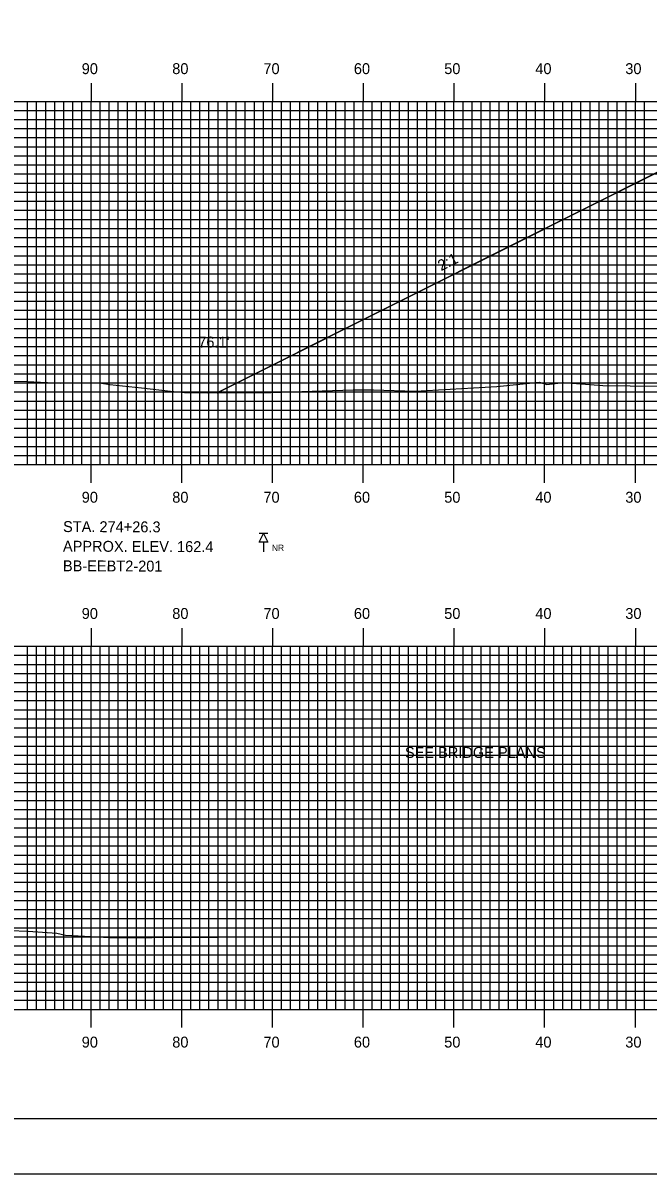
# Model space of a CAD drawing. Extents: x 1809406 to 1809749, y 442591 to 442811.
# Drawn here: x 1809474.3 to 1809543.2, y 442590.5 to 442717.3 of the extents above; entities that cross this region are included whole.
import ezdxf

# ---------------------------------------------------------------- set-up
doc = ezdxf.new("R2010")
doc.units = 0
for name, color, linetype in [('ANNOTATION', 7, 'Continuous'), ('BORDER', 7, 'Continuous'), ('BORING - NO REFUSAL', 7, 'Continuous'), ('D_Roadway_Centerline', 7, 'Continuous'), ('D_Roadway_SlopeLines', 7, 'Continuous'), ('D_Text_Standard', 7, 'Continuous'), ('H_V ANNOTATION', 7, 'Continuous'), ('MAJOR', 7, 'Continuous'), ('MINOR', 7, 'Continuous'), ('PLOT BOUNDARY', 7, 'Continuous'), ('S_Roadway_Centerline', 7, 'Continuous')]:
    doc.layers.add(name, color=color, linetype=linetype)

msp = doc.modelspace()

# ---------------------------------------------------------------- linework, layer by layer
at = {"layer": 'BORDER'}
msp.add_lwpolyline([(1809422.24, 442596.67), (1809742.24, 442596.67), (1809742.24, 442806.67), (1809422.24, 442806.67)], close=True, dxfattribs=at)
at = {"layer": 'BORING - NO REFUSAL'}
for p, q in [((1809501.32, 442661.07), (1809500.36, 442661.07)), ((1809500.84, 442660.11), (1809500.84, 442659.05))]:
    msp.add_line(p, q, dxfattribs=at)
msp.add_lwpolyline([(1809500.84, 442661.07), (1809501.32, 442660.11), (1809500.36, 442660.11)], close=True, dxfattribs=at)
at = {"layer": 'D_Roadway_Centerline'}
msp.add_lwpolyline([(1809495.74, 442676.58), (1809543.88, 442700.65), (1809548.84, 442703.13), (1809551.84, 442703.22), (1809559.84, 442703.47), (1809571.84, 442703.12), (1809583.84, 442702.77), (1809591.84, 442702.45), (1809594.84, 442702.33), (1809599.89, 442699.8), (1809643.63, 442677.93)], dxfattribs=at)
at = {"layer": 'D_Roadway_SlopeLines'}
msp.add_lwpolyline([(1809548.84, 442703.13), (1809495.74, 442676.58)], dxfattribs=at)
at = {"layer": 'MAJOR'}
for p, q in [((1809481.84, 442710.67), (1809481.84, 442708.67)), ((1809491.84, 442710.67), (1809491.84, 442708.67)), ((1809501.84, 442710.67), (1809501.84, 442708.67)), ((1809511.84, 442710.67), (1809511.84, 442708.67)), ((1809521.84, 442710.67), (1809521.84, 442708.67)), ((1809531.84, 442710.67), (1809531.84, 442708.67)), ((1809541.84, 442710.67), (1809541.84, 442708.67)), ((1809431.84, 442708.67), (1809711.84, 442708.67)), ((1809431.84, 442708.67), (1809711.84, 442708.67)), ((1809481.84, 442668.67), (1809481.84, 442708.67)), ((1809491.84, 442668.67), (1809491.84, 442708.67)), ((1809501.84, 442668.67), (1809501.84, 442708.67)), ((1809511.84, 442668.67), (1809511.84, 442708.67)), ((1809521.84, 442668.67), (1809521.84, 442708.67)), ((1809531.84, 442668.67), (1809531.84, 442708.67)), ((1809541.84, 442668.67), (1809541.84, 442708.67)), ((1809431.84, 442703.67), (1809711.84, 442703.67)), ((1809431.84, 442698.67), (1809711.84, 442698.67)), ((1809431.84, 442693.67), (1809711.84, 442693.67)), ((1809431.84, 442688.67), (1809711.84, 442688.67)), ((1809431.84, 442683.67), (1809711.84, 442683.67)), ((1809431.84, 442678.67), (1809711.84, 442678.67)), ((1809431.84, 442673.67), (1809711.84, 442673.67)), ((1809431.84, 442668.67), (1809711.84, 442668.67)), ((1809431.84, 442668.67), (1809711.84, 442668.67)), ((1809481.84, 442666.66), (1809481.84, 442668.67)), ((1809491.84, 442666.66), (1809491.84, 442668.67)), ((1809501.84, 442666.66), (1809501.84, 442668.67)), ((1809511.84, 442666.66), (1809511.84, 442668.67)), ((1809521.84, 442666.66), (1809521.84, 442668.67)), ((1809531.84, 442666.66), (1809531.84, 442668.67)), ((1809541.84, 442666.66), (1809541.84, 442668.67)), ((1809481.84, 442650.67), (1809481.84, 442648.67)), ((1809491.84, 442650.67), (1809491.84, 442648.67)), ((1809501.84, 442650.67), (1809501.84, 442648.67)), ((1809511.84, 442650.67), (1809511.84, 442648.67)), ((1809521.84, 442650.67), (1809521.84, 442648.67)), ((1809531.84, 442650.67), (1809531.84, 442648.67)), ((1809541.84, 442650.67), (1809541.84, 442648.67)), ((1809431.84, 442648.67), (1809711.84, 442648.67)), ((1809431.84, 442648.67), (1809711.84, 442648.67)), ((1809481.84, 442608.67), (1809481.84, 442648.67)), ((1809491.84, 442608.67), (1809491.84, 442648.67)), ((1809501.84, 442608.67), (1809501.84, 442648.67)), ((1809511.84, 442608.67), (1809511.84, 442648.67)), ((1809521.84, 442608.67), (1809521.84, 442648.67)), ((1809531.84, 442608.67), (1809531.84, 442648.67)), ((1809541.84, 442608.67), (1809541.84, 442648.67)), ((1809431.84, 442643.67), (1809711.84, 442643.67)), ((1809431.84, 442638.67), (1809711.84, 442638.67)), ((1809431.84, 442633.67), (1809711.84, 442633.67)), ((1809431.84, 442628.67), (1809711.84, 442628.67)), ((1809431.84, 442623.67), (1809711.84, 442623.67)), ((1809431.84, 442618.67), (1809711.84, 442618.67)), ((1809431.84, 442613.67), (1809711.84, 442613.67)), ((1809431.84, 442608.67), (1809711.84, 442608.67)), ((1809431.84, 442608.67), (1809711.84, 442608.67)), ((1809481.84, 442606.66), (1809481.84, 442608.67)), ((1809491.84, 442606.66), (1809491.84, 442608.67)), ((1809501.84, 442606.66), (1809501.84, 442608.67)), ((1809511.84, 442606.66), (1809511.84, 442608.67)), ((1809521.84, 442606.66), (1809521.84, 442608.67)), ((1809531.84, 442606.66), (1809531.84, 442608.67)), ((1809541.84, 442606.66), (1809541.84, 442608.67))]:
    msp.add_line(p, q, dxfattribs=at)
at = {"layer": 'MINOR'}
for p, q in [((1809474.84, 442668.67), (1809474.84, 442708.67)), ((1809475.84, 442668.67), (1809475.84, 442708.67)), ((1809476.84, 442668.67), (1809476.84, 442708.67)), ((1809477.84, 442668.67), (1809477.84, 442708.67)), ((1809478.84, 442668.67), (1809478.84, 442708.67)), ((1809479.84, 442668.67), (1809479.84, 442708.67)), ((1809480.84, 442668.67), (1809480.84, 442708.67)), ((1809482.84, 442668.67), (1809482.84, 442708.67)), ((1809483.84, 442668.67), (1809483.84, 442708.67)), ((1809484.84, 442668.67), (1809484.84, 442708.67)), ((1809485.84, 442668.67), (1809485.84, 442708.67)), ((1809486.84, 442668.67), (1809486.84, 442708.67)), ((1809487.84, 442668.67), (1809487.84, 442708.67)), ((1809488.84, 442668.67), (1809488.84, 442708.67)), ((1809489.84, 442668.67), (1809489.84, 442708.67)), ((1809490.84, 442668.67), (1809490.84, 442708.67)), ((1809492.84, 442668.67), (1809492.84, 442708.67)), ((1809493.84, 442668.67), (1809493.84, 442708.67)), ((1809494.84, 442668.67), (1809494.84, 442708.67)), ((1809495.84, 442668.67), (1809495.84, 442708.67)), ((1809496.84, 442668.67), (1809496.84, 442708.67)), ((1809497.84, 442668.67), (1809497.84, 442708.67)), ((1809498.84, 442668.67), (1809498.84, 442708.67)), ((1809499.84, 442668.67), (1809499.84, 442708.67)), ((1809500.84, 442668.67), (1809500.84, 442708.67)), ((1809502.84, 442668.67), (1809502.84, 442708.67)), ((1809503.84, 442668.67), (1809503.84, 442708.67)), ((1809504.84, 442668.67), (1809504.84, 442708.67)), ((1809505.84, 442668.67), (1809505.84, 442708.67)), ((1809506.84, 442668.67), (1809506.84, 442708.67)), ((1809507.84, 442668.67), (1809507.84, 442708.67)), ((1809508.84, 442668.67), (1809508.84, 442708.67)), ((1809509.84, 442668.67), (1809509.84, 442708.67)), ((1809510.84, 442668.67), (1809510.84, 442708.67)), ((1809512.84, 442668.67), (1809512.84, 442708.67)), ((1809513.84, 442668.67), (1809513.84, 442708.67)), ((1809514.84, 442668.67), (1809514.84, 442708.67)), ((1809515.84, 442668.67), (1809515.84, 442708.67)), ((1809516.84, 442668.67), (1809516.84, 442708.67)), ((1809517.84, 442668.67), (1809517.84, 442708.67)), ((1809518.84, 442668.67), (1809518.84, 442708.67)), ((1809519.84, 442668.67), (1809519.84, 442708.67)), ((1809520.84, 442668.67), (1809520.84, 442708.67)), ((1809522.84, 442668.67), (1809522.84, 442708.67)), ((1809523.84, 442668.67), (1809523.84, 442708.67)), ((1809524.84, 442668.67), (1809524.84, 442708.67)), ((1809525.84, 442668.67), (1809525.84, 442708.67)), ((1809526.84, 442668.67), (1809526.84, 442708.67)), ((1809527.84, 442668.67), (1809527.84, 442708.67)), ((1809528.84, 442668.67), (1809528.84, 442708.67)), ((1809529.84, 442668.67), (1809529.84, 442708.67)), ((1809530.84, 442668.67), (1809530.84, 442708.67)), ((1809532.84, 442668.67), (1809532.84, 442708.67)), ((1809533.84, 442668.67), (1809533.84, 442708.67)), ((1809534.84, 442668.67), (1809534.84, 442708.67)), ((1809535.84, 442668.67), (1809535.84, 442708.67)), ((1809536.84, 442668.67), (1809536.84, 442708.67)), ((1809537.84, 442668.67), (1809537.84, 442708.67)), ((1809538.84, 442668.67), (1809538.84, 442708.67)), ((1809539.84, 442668.67), (1809539.84, 442708.67)), ((1809540.84, 442668.67), (1809540.84, 442708.67)), ((1809542.84, 442668.67), (1809542.84, 442708.67)), ((1809431.84, 442707.67), (1809711.84, 442707.67)), ((1809431.84, 442706.67), (1809711.84, 442706.67)), ((1809431.84, 442705.67), (1809711.84, 442705.67)), ((1809431.84, 442704.67), (1809711.84, 442704.67)), ((1809431.84, 442702.67), (1809711.84, 442702.67)), ((1809431.84, 442701.67), (1809711.84, 442701.67)), ((1809431.84, 442700.67), (1809711.84, 442700.67)), ((1809431.84, 442699.67), (1809711.84, 442699.67)), ((1809431.84, 442697.67), (1809711.84, 442697.67)), ((1809431.84, 442696.67), (1809711.84, 442696.67)), ((1809431.84, 442695.67), (1809711.84, 442695.67)), ((1809431.84, 442694.67), (1809711.84, 442694.67)), ((1809431.84, 442692.67), (1809711.84, 442692.67)), ((1809431.84, 442691.67), (1809711.84, 442691.67)), ((1809431.84, 442690.67), (1809711.84, 442690.67)), ((1809431.84, 442689.67), (1809711.84, 442689.67)), ((1809431.84, 442687.67), (1809711.84, 442687.67)), ((1809431.84, 442686.67), (1809711.84, 442686.67)), ((1809431.84, 442685.67), (1809711.84, 442685.67)), ((1809431.84, 442684.67), (1809711.84, 442684.67)), ((1809431.84, 442682.67), (1809711.84, 442682.67)), ((1809431.84, 442681.67), (1809711.84, 442681.67)), ((1809431.84, 442680.67), (1809711.84, 442680.67)), ((1809431.84, 442679.67), (1809711.84, 442679.67)), ((1809431.84, 442677.67), (1809711.84, 442677.67)), ((1809431.84, 442676.67), (1809711.84, 442676.67)), ((1809431.84, 442675.67), (1809711.84, 442675.67)), ((1809431.84, 442674.67), (1809711.84, 442674.67)), ((1809431.84, 442672.67), (1809711.84, 442672.67)), ((1809431.84, 442671.67), (1809711.84, 442671.67)), ((1809431.84, 442670.67), (1809711.84, 442670.67)), ((1809431.84, 442669.67), (1809711.84, 442669.67)), ((1809474.84, 442608.67), (1809474.84, 442648.67)), ((1809475.84, 442608.67), (1809475.84, 442648.67)), ((1809476.84, 442608.67), (1809476.84, 442648.67)), ((1809477.84, 442608.67), (1809477.84, 442648.67)), ((1809478.84, 442608.67), (1809478.84, 442648.67)), ((1809479.84, 442608.67), (1809479.84, 442648.67)), ((1809480.84, 442608.67), (1809480.84, 442648.67)), ((1809482.84, 442608.67), (1809482.84, 442648.67)), ((1809483.84, 442608.67), (1809483.84, 442648.67)), ((1809484.84, 442608.67), (1809484.84, 442648.67)), ((1809485.84, 442608.67), (1809485.84, 442648.67)), ((1809486.84, 442608.67), (1809486.84, 442648.67)), ((1809487.84, 442608.67), (1809487.84, 442648.67)), ((1809488.84, 442608.67), (1809488.84, 442648.67)), ((1809489.84, 442608.67), (1809489.84, 442648.67)), ((1809490.84, 442608.67), (1809490.84, 442648.67)), ((1809492.84, 442608.67), (1809492.84, 442648.67)), ((1809493.84, 442608.67), (1809493.84, 442648.67)), ((1809494.84, 442608.67), (1809494.84, 442648.67)), ((1809495.84, 442608.67), (1809495.84, 442648.67)), ((1809496.84, 442608.67), (1809496.84, 442648.67)), ((1809497.84, 442608.67), (1809497.84, 442648.67)), ((1809498.84, 442608.67), (1809498.84, 442648.67)), ((1809499.84, 442608.67), (1809499.84, 442648.67)), ((1809500.84, 442608.67), (1809500.84, 442648.67)), ((1809502.84, 442608.67), (1809502.84, 442648.67)), ((1809503.84, 442608.67), (1809503.84, 442648.67)), ((1809504.84, 442608.67), (1809504.84, 442648.67)), ((1809505.84, 442608.67), (1809505.84, 442648.67)), ((1809506.84, 442608.67), (1809506.84, 442648.67)), ((1809507.84, 442608.67), (1809507.84, 442648.67)), ((1809508.84, 442608.67), (1809508.84, 442648.67)), ((1809509.84, 442608.67), (1809509.84, 442648.67)), ((1809510.84, 442608.67), (1809510.84, 442648.67)), ((1809512.84, 442608.67), (1809512.84, 442648.67)), ((1809513.84, 442608.67), (1809513.84, 442648.67)), ((1809514.84, 442608.67), (1809514.84, 442648.67)), ((1809515.84, 442608.67), (1809515.84, 442648.67)), ((1809516.84, 442608.67), (1809516.84, 442648.67)), ((1809517.84, 442608.67), (1809517.84, 442648.67)), ((1809518.84, 442608.67), (1809518.84, 442648.67)), ((1809519.84, 442608.67), (1809519.84, 442648.67)), ((1809520.84, 442608.67), (1809520.84, 442648.67)), ((1809522.84, 442608.67), (1809522.84, 442648.67)), ((1809523.84, 442608.67), (1809523.84, 442648.67)), ((1809524.84, 442608.67), (1809524.84, 442648.67)), ((1809525.84, 442608.67), (1809525.84, 442648.67)), ((1809526.84, 442608.67), (1809526.84, 442648.67)), ((1809527.84, 442608.67), (1809527.84, 442648.67)), ((1809528.84, 442608.67), (1809528.84, 442648.67)), ((1809529.84, 442608.67), (1809529.84, 442648.67)), ((1809530.84, 442608.67), (1809530.84, 442648.67)), ((1809532.84, 442608.67), (1809532.84, 442648.67)), ((1809533.84, 442608.67), (1809533.84, 442648.67)), ((1809534.84, 442608.67), (1809534.84, 442648.67)), ((1809535.84, 442608.67), (1809535.84, 442648.67)), ((1809536.84, 442608.67), (1809536.84, 442648.67)), ((1809537.84, 442608.67), (1809537.84, 442648.67)), ((1809538.84, 442608.67), (1809538.84, 442648.67)), ((1809539.84, 442608.67), (1809539.84, 442648.67)), ((1809540.84, 442608.67), (1809540.84, 442648.67)), ((1809542.84, 442608.67), (1809542.84, 442648.67)), ((1809431.84, 442647.67), (1809711.84, 442647.67)), ((1809431.84, 442646.67), (1809711.84, 442646.67)), ((1809431.84, 442645.67), (1809711.84, 442645.67)), ((1809431.84, 442644.67), (1809711.84, 442644.67)), ((1809431.84, 442642.67), (1809711.84, 442642.67)), ((1809431.84, 442641.67), (1809711.84, 442641.67)), ((1809431.84, 442640.67), (1809711.84, 442640.67)), ((1809431.84, 442639.67), (1809711.84, 442639.67)), ((1809431.84, 442637.67), (1809711.84, 442637.67)), ((1809431.84, 442636.67), (1809711.84, 442636.67)), ((1809431.84, 442635.67), (1809711.84, 442635.67)), ((1809431.84, 442634.67), (1809711.84, 442634.67)), ((1809431.84, 442632.67), (1809711.84, 442632.67)), ((1809431.84, 442631.67), (1809711.84, 442631.67)), ((1809431.84, 442630.67), (1809711.84, 442630.67)), ((1809431.84, 442629.67), (1809711.84, 442629.67)), ((1809431.84, 442627.67), (1809711.84, 442627.67)), ((1809431.84, 442626.67), (1809711.84, 442626.67)), ((1809431.84, 442625.67), (1809711.84, 442625.67)), ((1809431.84, 442624.67), (1809711.84, 442624.67)), ((1809431.84, 442622.67), (1809711.84, 442622.67)), ((1809431.84, 442621.67), (1809711.84, 442621.67)), ((1809431.84, 442620.67), (1809711.84, 442620.67)), ((1809431.84, 442619.67), (1809711.84, 442619.67)), ((1809431.84, 442617.67), (1809711.84, 442617.67)), ((1809431.84, 442616.67), (1809711.84, 442616.67)), ((1809431.84, 442615.67), (1809711.84, 442615.67)), ((1809431.84, 442614.67), (1809711.84, 442614.67)), ((1809431.84, 442612.67), (1809711.84, 442612.67)), ((1809431.84, 442611.67), (1809711.84, 442611.67)), ((1809431.84, 442610.67), (1809711.84, 442610.67)), ((1809431.84, 442609.67), (1809711.84, 442609.67))]:
    msp.add_line(p, q, dxfattribs=at)
at = {"layer": 'PLOT BOUNDARY'}
msp.add_lwpolyline([(1809406.05, 442590.55), (1809746.05, 442590.55), (1809746.05, 442810.55), (1809406.05, 442810.55)], close=True, dxfattribs=at)
at = {"layer": 'S_Roadway_Centerline'}
for points in [[(1809460.46, 442677.97), (1809474.81, 442677.8), (1809478.49, 442677.65), (1809482.77, 442677.67), (1809483.92, 442677.5), (1809487.39, 442677.12), (1809490.6, 442676.77), (1809492.14, 442676.59), (1809494.71, 442676.58), (1809500.8, 442676.6), (1809501.37, 442676.6), (1809501.65, 442676.6), (1809510.72, 442676.91), (1809511.44, 442676.91), (1809512.96, 442676.91), (1809517.58, 442676.77), (1809526.56, 442677.27), (1809531.28, 442677.75), (1809532.09, 442677.47), (1809533.9, 442677.72), (1809538.25, 442677.36), (1809553.38, 442677.19)], [(1809431.84, 442618.04), (1809433.87, 442617.99), (1809437.96, 442617.83), (1809441.14, 442617.8), (1809448.42, 442617.78), (1809454.43, 442617.54), (1809456.61, 442617.26), (1809465.13, 442617.57), (1809467.73, 442617.51), (1809468.81, 442617.51), (1809474.91, 442617.3), (1809478.06, 442617.07), (1809479.02, 442616.84), (1809483.92, 442616.59), (1809487.66, 442616.59), (1809488.59, 442616.59), (1809502.91, 442616.65), (1809506.56, 442616.66), (1809516.95, 442616.65), (1809524.81, 442616.64), (1809531.99, 442616.66), (1809543.3, 442616.68)]]:
    msp.add_lwpolyline(points, dxfattribs=at)

# ---------------------------------------------------------------- texts
at = {"layer": 'ANNOTATION'}
msp.add_text('2:1', height=1.2, rotation=26.5651, dxfattribs=at).set_placement((1809520.43, 442689.96))
at = {"layer": 'BORING - NO REFUSAL'}
for s, p in [('STA. 274+26.3', (1809478.75, 442661.24)), ('APPROX. ELEV. 162.4', (1809478.74, 442659.08)), ('BB-EEBT2-201', (1809478.74, 442656.92))]:
    msp.add_text(s, height=1.2, rotation=359.8142, dxfattribs=at).set_placement(p)
msp.add_text('NR', height=0.7, dxfattribs=at).set_placement((1809501.77, 442659.15))
at = {"layer": 'D_Text_Standard'}
for s, p in [("76.1'", (1809493.66, 442681.56)), ('SEE BRIDGE PLANS', (1809516.44, 442636.37))]:
    msp.add_text(s, height=1.2, dxfattribs=at).set_placement(p)
at = {"layer": 'H_V ANNOTATION'}
for s, p in [('90', (1809480.81, 442711.67)), ('80', (1809490.79, 442711.67)), ('70', (1809500.84, 442711.67)), ('60', (1809510.81, 442711.67)), ('50', (1809520.77, 442711.67)), ('40', (1809530.81, 442711.67)), ('30', (1809540.73, 442711.67)), ('90', (1809480.81, 442664.47)), ('80', (1809490.79, 442664.47)), ('70', (1809500.84, 442664.47)), ('60', (1809510.81, 442664.47)), ('50', (1809520.77, 442664.47)), ('40', (1809530.81, 442664.47)), ('30', (1809540.73, 442664.47)), ('90', (1809480.81, 442651.67)), ('80', (1809490.79, 442651.67)), ('70', (1809500.84, 442651.67)), ('60', (1809510.81, 442651.67)), ('50', (1809520.77, 442651.67)), ('40', (1809530.81, 442651.67)), ('30', (1809540.73, 442651.67)), ('90', (1809480.81, 442604.47)), ('80', (1809490.79, 442604.47)), ('70', (1809500.84, 442604.47)), ('60', (1809510.81, 442604.47)), ('50', (1809520.77, 442604.47)), ('40', (1809530.81, 442604.47)), ('30', (1809540.73, 442604.47))]:
    msp.add_text(s, height=1.2, dxfattribs=at).set_placement(p)

doc.saveas('drawing.dxf')
